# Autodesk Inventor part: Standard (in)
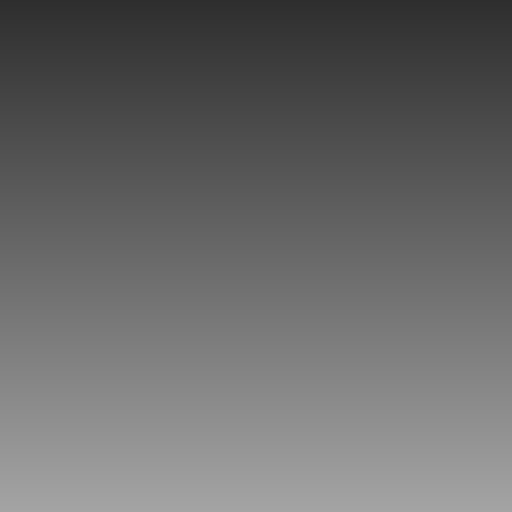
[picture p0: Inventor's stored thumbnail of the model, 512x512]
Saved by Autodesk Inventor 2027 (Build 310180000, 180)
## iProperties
Shininess: 64.0
Length Units: 11272
Angle Units: 11279
Time Units: 11290
Mass Units: 11286
Length Display Precision: 3
Angle Display Precision: 2
Compacted: True
Part Number: Standard (in)
Document SubType Name: Modeling
Created: 2002-08
Density: 1 g/cm^3
Material: Generic
Appearance: Default
Density: 0.0
Volumn: 0.0
Area: 0.0
PropertySet Name: Model Information
Control State: 0
Master: False
Checked Out: False
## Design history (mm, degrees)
